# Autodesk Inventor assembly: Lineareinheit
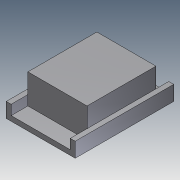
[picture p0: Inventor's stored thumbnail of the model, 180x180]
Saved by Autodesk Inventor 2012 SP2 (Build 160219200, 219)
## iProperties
Created: 2012-10
Part Number: Lineareinheit
Description: =<BEZEICHNUNG DEUTSCH>
Document SubType Name: Assembly
Designer: Massmann
Manufacturer: Standard
Standards Organization: Custom
Mass: 171 g
Surface Area: 361 cm^2
Volume: 171 cm^3
Density: 1 g/cm^3
IdentNr: =<SAP MATERIALNUMMER>
Author: Massmann
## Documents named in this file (3)
- C:\Local\PROFILE_Workspace\Inventor\Lineareinheit.iam
- C:\Local\PROFILE_Workspace\Inventor\Führung.ipt
- C:\Local\PROFILE_Workspace\Inventor\Schlitten.ipt
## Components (2 placed, 2 different names)
1. Führung:1 — Passend:1, Passend:5
2. Schlitten:1 — Passend:1, Passend:3, Passend:5
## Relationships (3: Mate 3)
- Passend:1 [Mate]: Führung:1 ↔ Schlitten:1
- Passend:3 [Mate]: Schlitten:1
- Passend:5 [Mate]: Führung:1 ↔ Schlitten:1
